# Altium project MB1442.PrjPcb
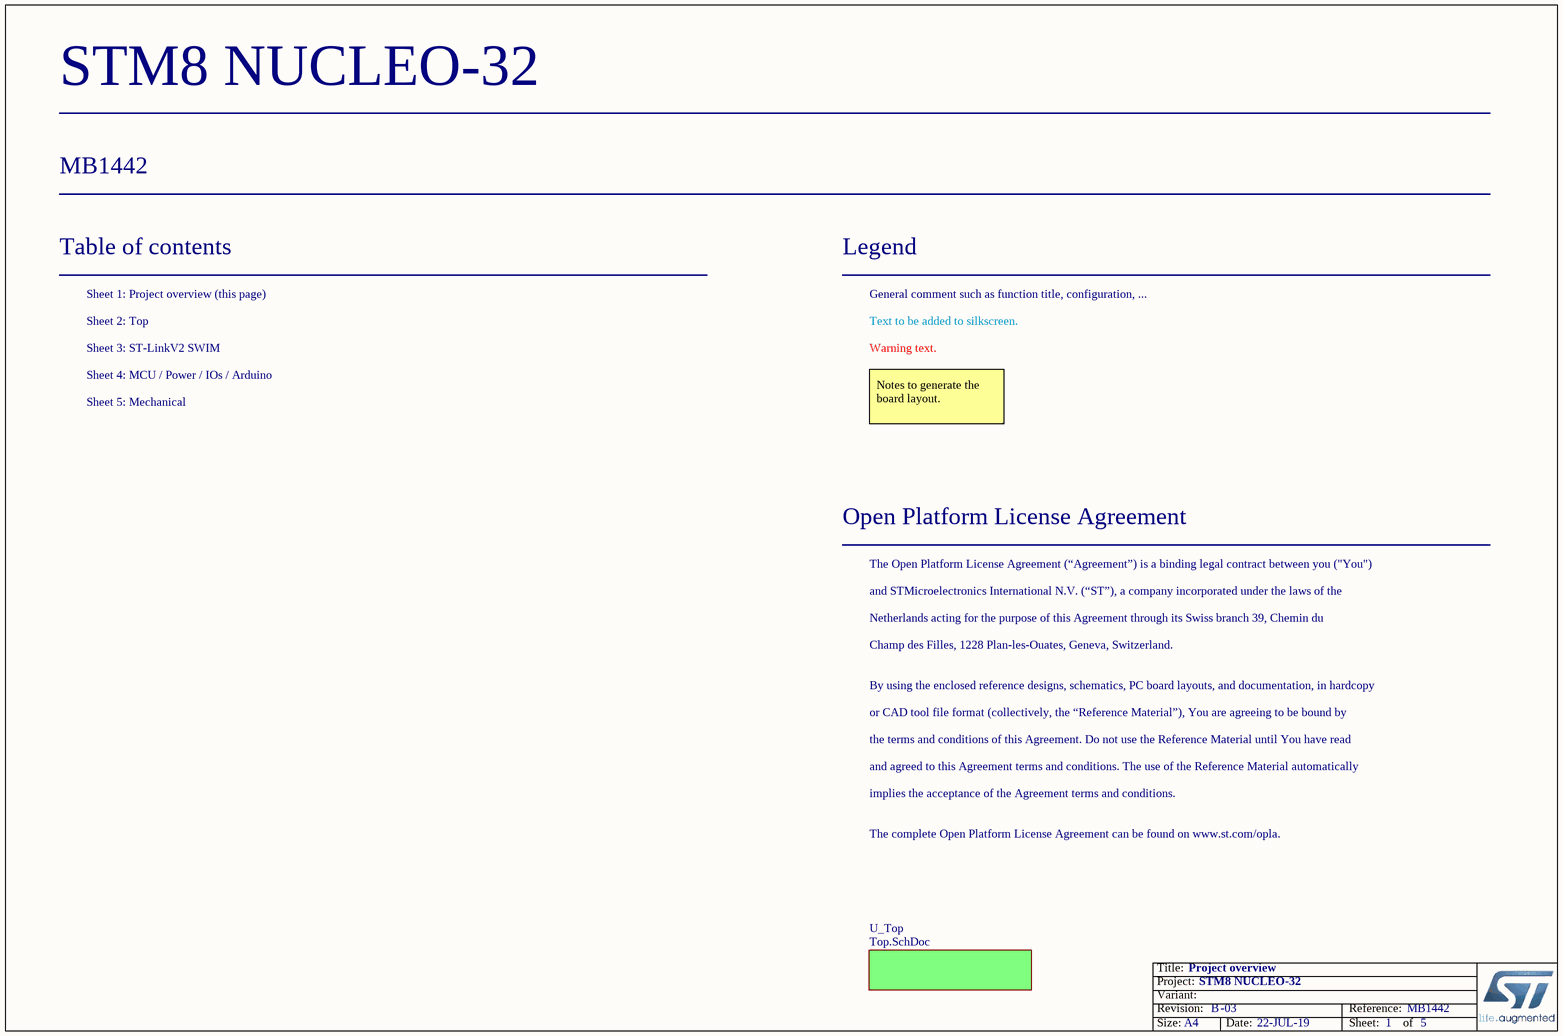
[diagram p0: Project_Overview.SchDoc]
Board_Assembly_Revision: 03; Board_Document_Date: 22-JUL-19; Board_Name: STM8 NUCLEO-32; Board_PCB_Revision: B; Board_Reference: MB1442
5 sheets, 96 parts. Net scope: flat (ports and power ports of the same name join across sheets).
Board file: MB1442.PcbDoc
Sheets:
  Project_Overview.SchDoc
    U_Top = Top.SchDoc
      U_ST-LinkV2-1_SWIM = ST-LinkV2-1_SWIM.SchDoc
      U_MCU_Power_IOs_Arduino = MCU_Power_IOs_Arduino.SchDoc
      U_Mechanical = Mechanical.SchDoc

## Sheet Project_Overview.SchDoc: Project overview
size A4; Date: Not used; ApprovedBy: Not used; CheckedBy: Not used; Author: Not used; CompanyName: STMicroelectronics; DrawnBy: Not used; Engineer: Not used; Organization: Not used; Address1: Not used; Address2: Not used; Address3: Not used; Address4: Not used; DocumentNumber: Not used; Revision: Not used; SheetNumber: 1; SheetTotal: 5

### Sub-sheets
U_Top = Top.SchDoc: no entries

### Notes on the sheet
- Table of contents
- Sheet 1: Project overview (this page)
- Legend
- General comment such as function title, configuration, ...
- Sheet 2: Top
- Sheet 3: ST-LinkV2 SWIM
- Sheet 4: MCU / Power / IOs / Arduino
- Text to be added to silkscreen.
- Warning text.
- Sheet 5: Mechanical
- Notes to generate the board layout.
- Open Platform License Agreement
- The Open Platform License Agreement (“Agreement”) is a binding legal contract between you ("You")
- and STMicroelectronics International N.V. (“ST”), a company incorporated under the laws of the
- Netherlands acting for the purpose of this Agreement through its Swiss branch 39, Chemin du
- Champ des Filles, 1228 Plan-les-Ouates, Geneva, Switzerland.
- By using the enclosed reference designs, schematics, PC board layouts, and documentation, in hardcopy
- or CAD tool file format (collectively, the “Reference Material”), You are agreeing to be bound by
- the terms and conditions of this Agreement. Do not use the Reference Material until You have read
- and agreed to this Agreement terms and conditions. The use of the Reference Material automatically
- implies the acceptance of the Agreement terms and conditions.
- The complete Open Platform License Agreement can be found on www.st.com/opla.

## Sheet Top.SchDoc: Top
size A4; Date: Not used; ApprovedBy: Not used; CheckedBy: Not used; Author: Not used; CompanyName: STMicroelectronics; DrawnBy: Not used; Engineer: Not used; Organization: Not used; Address1: Not used; Address2: Not used; Address3: Not used; Address4: Not used; DocumentNumber: Not used; Revision: Not used; SheetNumber: 2; SheetTotal: 5
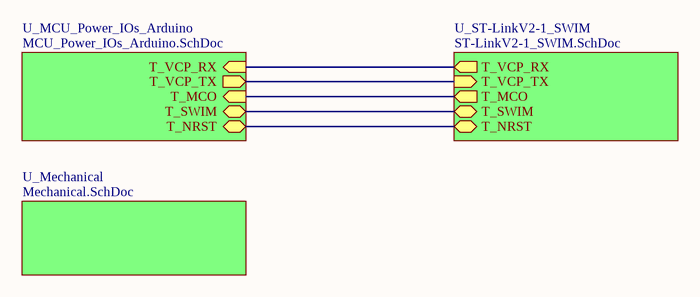
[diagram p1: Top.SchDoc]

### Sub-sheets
U_MCU_Power_IOs_Arduino = MCU_Power_IOs_Arduino.SchDoc: T_SWIM (bidir), T_NRST (bidir), T_MCO (in), T_VCP_RX (in), T_VCP_TX (out)
U_Mechanical = Mechanical.SchDoc: no entries
U_ST-LinkV2-1_SWIM = ST-LinkV2-1_SWIM.SchDoc: T_VCP_RX (out), T_VCP_TX (in), T_MCO (out), T_SWIM (bidir), T_NRST (bidir)

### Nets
(unnamed): sheet U_ST-LinkV2-1_SWIM/T_VCP_RX, sheet U_MCU_Power_IOs_Arduino/T_VCP_RX
(unnamed): sheet U_ST-LinkV2-1_SWIM/T_VCP_TX, sheet U_MCU_Power_IOs_Arduino/T_VCP_TX  [a separate net that carries the same name]
(unnamed): sheet U_ST-LinkV2-1_SWIM/T_MCO, sheet U_MCU_Power_IOs_Arduino/T_MCO  [a separate net that carries the same name]
(unnamed): sheet U_ST-LinkV2-1_SWIM/T_SWIM, sheet U_MCU_Power_IOs_Arduino/T_SWIM  [a separate net that carries the same name]
(unnamed): sheet U_ST-LinkV2-1_SWIM/T_NRST, sheet U_MCU_Power_IOs_Arduino/T_NRST  [a separate net that carries the same name]

## Sheet ST-LinkV2-1_SWIM.SchDoc: ST-Link/V2-1 SWIM
size A4; Date: Not used; ApprovedBy: Not used; CheckedBy: Not used; Author: Not used; CompanyName: STMicroelectronics; DrawnBy: Not used; Engineer: Not used; Organization: Not used; Address1: Not used; Address2: Not used; Address3: Not used; Address4: Not used; DocumentNumber: Not used; Revision: Not used; SheetNumber: 4; SheetTotal: 5
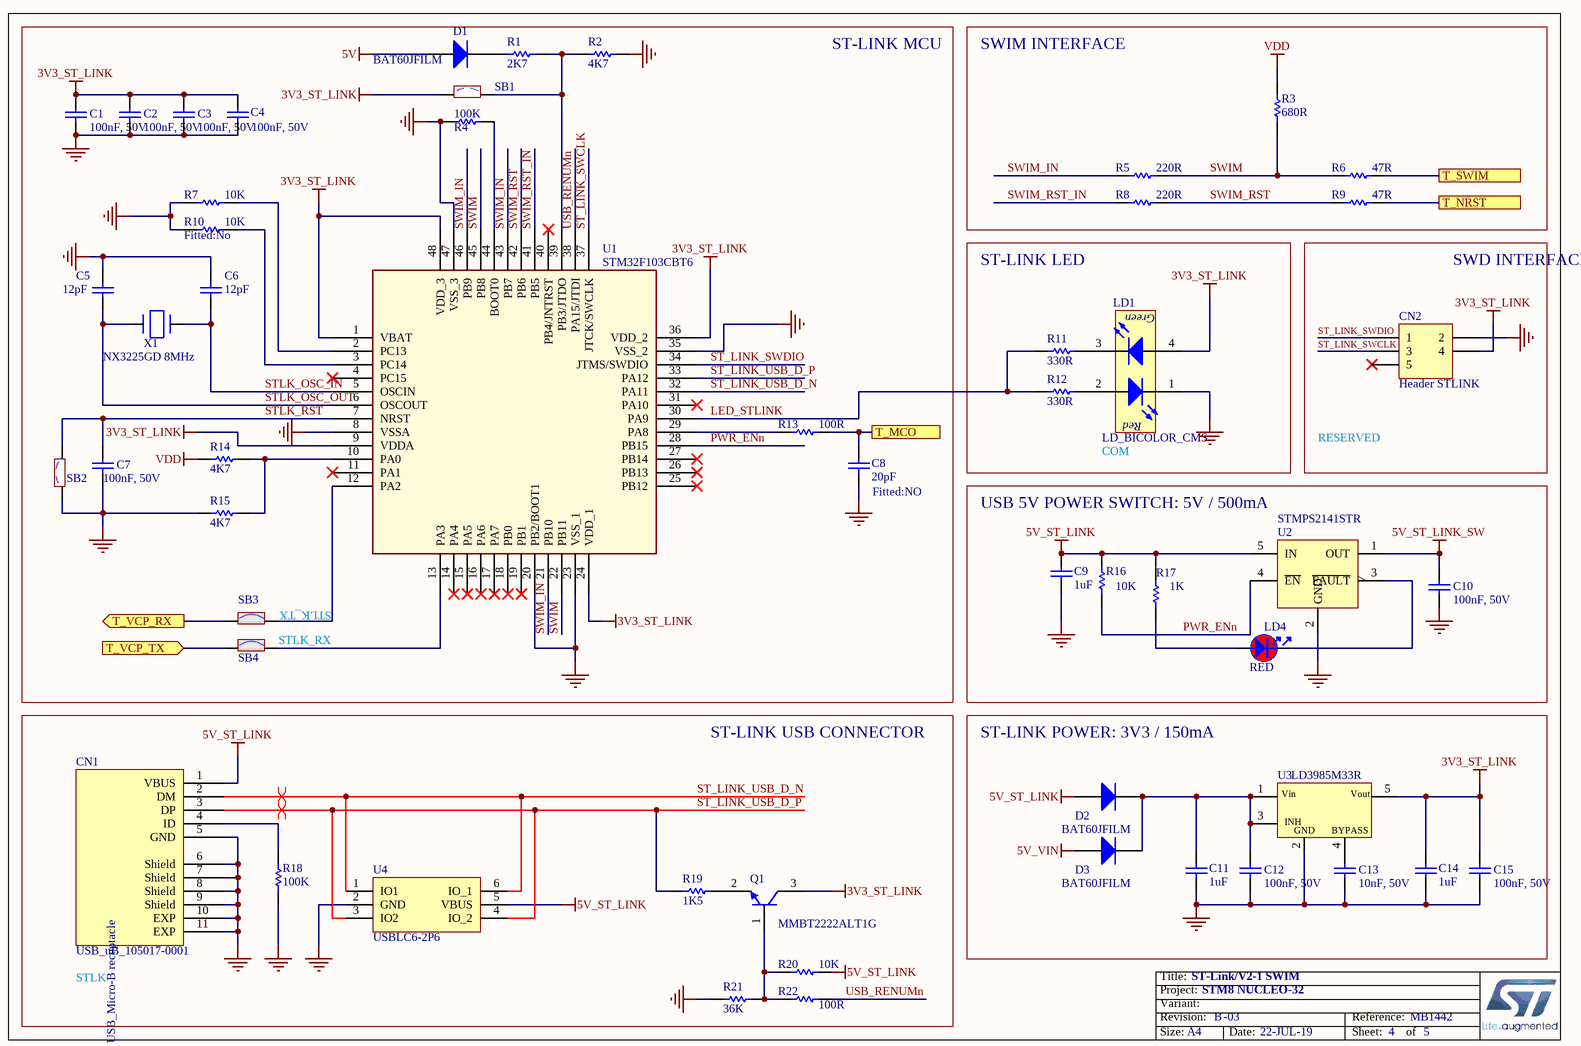
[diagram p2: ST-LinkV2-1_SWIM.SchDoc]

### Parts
C1  value 100nF, 50V  [C0603]  (hidden comment: Capacitor)
C2  value 100nF, 50V  [C0603]  (hidden comment: Capacitor)
C3  value 100nF, 50V  [C0603]  (hidden comment: Capacitor)
C4  value 100nF, 50V  [C0603]  (hidden comment: Capacitor)
C5  value 12pF  [C0402]  (hidden comment: Capacitor)
C6  value 12pF  [C0402]  (hidden comment: Capacitor)
C7  value 100nF, 50V  [C0603]  (hidden comment: Capacitor)
C8  value 20pF  [C0603]  (hidden comment: Capacitor)
C9  value 1uF  [C0603]  (hidden comment: Capacitor)
C10  value 100nF, 50V  [C0603]  (hidden comment: Capacitor)
C11  value 1uF  [C0603]  (hidden comment: Capacitor)
C12  value 100nF, 50V  [C0603]  (hidden comment: Capacitor)
C13  value 10nF, 50V  [C0603]  (hidden comment: Capacitor)
C14  value 1uF  [C0603]  (hidden comment: Capacitor)
C15  value 100nF, 50V  [C0603]  (hidden comment: Capacitor)
CN1  value USB_uB_105017-0001  [CON_USBMICROB_MOLEX_105017-0001_H2P90]  (hidden comment: USB_uB_105017.0001)
CN2  Header STLINK  [HDR_1x5_2R54_V_M]
D1  BAT60JFILM  [DIO_SOD323]
D2  BAT60JFILM  [DIO_SOD323]
D3  BAT60JFILM  [DIO_SOD323]
LD1  LD_BICOLOR_CMS  [LED_BI-GR_HSMF-A201-A00J1]
LD4  value RED  [LED_0603_RED_H0P4]  (hidden comment: LED_red)
Q1  value MMBT2222ALT1G  [NPN_SOT23]  (hidden comment: 9013-SOT23)
R1  value 2K7  [R0603]  (hidden comment: Resistor)
R2  value 4K7  [R0603]  (hidden comment: Resistor)
R3  value 680R  [R0603]  (hidden comment: Resistor)
R4  value 100K  [R0603]  (hidden comment: Resistor)
R5  value 220R  [R0603]  (hidden comment: Resistor)
R6  value 47R  [R0603]  (hidden comment: Resistor)
R7  value 10K  [R0603]  (hidden comment: Resistor)
R8  value 220R  [R0603]  (hidden comment: Resistor)
R9  value 47R  [R0603]  (hidden comment: Resistor)
R10  value 10K  [R0603]  (hidden comment: Resistor)
R11  value 330R  [R0603]  (hidden comment: Resistor)
R12  value 330R  [R0603]  (hidden comment: Resistor)
R13  value 100R  [R0603]  (hidden comment: Resistor)
R14  value 4K7  [R0603]  (hidden comment: Resistor)
R15  value 4K7  [R0603]  (hidden comment: Resistor)
R16  value 10K  [R0603]  (hidden comment: Resistor)
R17  value 1K  [R0603]  (hidden comment: Resistor)
R18  value 100K  [R0603]  (hidden comment: Resistor)
R19  value 1K5  [R0603]  (hidden comment: Resistor)
R20  value 10K  [R0603]  (hidden comment: Resistor)
R21  value 36K  [R0603]  (hidden comment: Resistor)
R22  value 100R  [R0603]  (hidden comment: Resistor)
SB1  SB_OFF  [SOLDER-BRIDGE_R0603-0R]  (value not drawn)
SB2  SB_OFF  [SOLDER-BRIDGE_R0603-0R]  (value not drawn)
SB3  SB_ON  [SOLDER-BRIDGE_R0603-0R]  (value not drawn)
SB4  SB_ON  [SOLDER-BRIDGE_R0603-0R]  (value not drawn)
U1  STM32F103CBT6  [ICC_LQFP48_7X7_P050]
U2  STMPS2141STR  [MOS_SOT23-5L]
U3  LD3985M33R  [REG_SOT23-5L]
U4  USBLC6-2P6  [ESD_SOT666]
X1  value NX3225GD 8MHz  [CRY_NX3225GD_2P]  (hidden comment: XTAL_2_PINS)

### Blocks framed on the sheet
ST-LINK MCU: C1-C8 D1 R1 R2 R4 R7 R10 R13-R15 SB1-SB4 U1 X1
SWIM INTERFACE: R3 R5 R6 R8 R9
ST-LINK LED: LD1 R11 R12
SWD INTERFACE: CN2
USB 5V POWER SWITCH: 5V / 500mA: C9 C10 LD4 R16 R17 U2
ST-LINK USB CONNECTOR: CN1 Q1 R18-R22 U4
ST-LINK POWER: 3V3 / 150mA: C11-C15 D2 D3 U3

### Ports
T_MCO, T_NRST, T_SWIM, T_VCP_RX (out), T_VCP_TX (in)

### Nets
3V3_ST_LINK: C1.2 C2.2 C3.2 C4.2 C14.2 C15.2 CN2.4 LD1.4(YellowGreen_anode) Q1.3(C) SB1.1 U1.1(VBAT) U1.9(VDDA) U1.24(VDD_1) U1.36(VDD_2) U1.48(VDD_3) U3.5(Vout)
5V: D1.1(A)
5V_ST_LINK: C9.2 CN1.1(VBUS) D2.1(A) R16.2 R17.2 R20.2 U2.5(IN) U4.5(VBUS)
5V_ST_LINK_SW: C10.2 U2.1(OUT)
5V_VIN: D3.1(A)
GND: C1.1 C2.1 C3.1 C4.1 C5.2 C6.2 C7.1 C8.1 C9.1 C10.1 C11.1 C12.1 C13.1 C14.1 C15.1 CN1.5(GND) CN1.6(Shield) CN1.7(Shield) CN1.8(Shield) CN1.9(Shield) CN1.10(EXP) CN1.11(EXP) CN2.2 LD1.1(RED_cathode) R2.2 R4.1 R7.1 R10.1 R15.1 R18.1 R21.1 SB2.1 U1.8(VSSA) U1.20(PB2/BOOT1) U1.23(VSS_1) U1.35(VSS_2) U1.47(VSS_3) U2.2(GND) U3.2(GND) U4.2(GND)
VDD: R3.2 R14.1
LED_STLINK: R11.1 R12.1 U1.30(PA9)
PWR_ENn: R16.1 U1.28(PB15) U2.4(~{EN})
ST_LINK_SWCLK: CN2.3 U1.37(JTCK/SWCLK)
ST_LINK_SWDIO: CN2.1 U1.34(JTMS/SWDIO)
ST_LINK_USB_D_N: CN1.2(DM) U1.32(PA11) U4.1(IO1) U4.6(IO_1)
ST_LINK_USB_D_P: CN1.3(DP) R19.1 U1.33(PA12) U4.3(IO2) U4.4(IO_2)
STLK_OSC_IN: C6.1 U1.5(OSCIN) X1.1(X1)
STLK_OSC_OUT: C5.1 U1.6(OSCOUT) X1.2(X2)
STLK_RST: C7.2 SB2.2 U1.7(NRST)
SWIM: R3.1 R5.2 R6.1 U1.22(PB11) U1.45(PB8)
SWIM_IN: R5.1 U1.21(PB10) U1.43(PB7) U1.46(PB9)
SWIM_RST: R8.2 R9.1 U1.42(PB6)
SWIM_RST_IN: R8.1 U1.41(PB5)
T_MCO: C8.2 R13.2 ; port T_MCO
T_NRST: R9.2 ; port T_NRST
T_SWIM: R6.2 ; port T_SWIM
T_VCP_RX: SB3.1 ; port T_VCP_RX
T_VCP_TX: SB4.1 ; port T_VCP_TX
USB_RENUMn: R22.2 U1.38(PA15/JTDI)
NetC11_2: C11.2 C12.2 D2.2(K) D3.2(K) U3.1(Vin) U3.3(CE)
NetC13_2: C13.2 U3.4(BYPASS)
NetCN1_4: CN1.4(ID) R18.2
NetD1_2: D1.2(K) R1.1
NetLD1_2: LD1.2(Red_anode) R12.2
NetLD1_3: LD1.3(YellowGreen_cathode) R11.2
NetLD4_1: LD4.1 R17.1
NetLD4_2: LD4.2 U2.3(~{FAULT})
NetQ1_1: Q1.1(B) R20.1 R21.2 R22.1
NetQ1_2: Q1.2(E) R19.2
NetR1_2: R1.2 R2.1 SB1.2 U1.39(PB3/JTDO)
NetR4_2: R4.2 U1.44(BOOT0)
NetR7_2: R7.2 U1.2(PC13)
NetR10_2: R10.2 U1.3(PC14)
NetR13_1: R13.1 U1.29(PA8)
NetR14_2: R14.2 R15.2 U1.10(PA0)
NetSB3_2: SB3.2 U1.12(PA2)
NetSB4_2: SB4.2 U1.13(PA3)

Not connected (* = marked no-connect by the designer): CN2 5*; U1 4(PC15)* 11(PA1)* 14(PA4)* 15(PA5)* 16(PA6)* 17(PA7)* 18(PB0)* 19(PB1)* 25(PB12)* 26(PB13)* 27(PB14)* 31(PA10)* 40(PB4/JNTRST)*

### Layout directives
differential pair: ST_LINK_USB_D_N, ST_LINK_USB_D_P

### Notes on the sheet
- (near R10) Fitted:No
- COM
- RESERVED
- (near C8) Fitted:NO
- STLK_RX
- STLK_TX
- STLK

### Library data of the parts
C1-C4 C7 C10 C12 C15 = MCD-01099: Capacitor,100nF,50V,X7R,10%,0603; Manufacturer_Part_Number: CC0603KRX7R9BB104; Manufacturer: YAGEO; Provided_By: SUBCO
C5 C6 = MCD-00200: Capacitor, MLCC, 12pF, 50V, NPO, 5%, 0402, T=0,5mm; Manufacturer_Part_Number: CC0402JRNPO9BN120; Manufacturer: YAGEO; Provided_By: SUBCO; ECCN_US: EAR99; ECCN_EU: NEC
C8 = MCD-00638: Capacitor, MLCC, 20pF, 50V, NPO, 5%, 0603, T=0,8mm; Manufacturer_Part_Number: CC0603JRNPO9BN200; Manufacturer: YAGEO; ECCN_US: EAR99; ECCN_EU: NEC; Provided_By: SUBCO
C9 C11 C14 = MCD-01053: Capacitor, C-series, X5R, 1µF, 50V, 10%, 0603, T=0.8mm; Manufacturer_Part_Number: C1608X5R1H105K080AB; Manufacturer: TDK; ECCN_US: EAR99; ECCN_EU: NEC; Provided_By: SUBCO
C13 = MCD-01102: Capacitor,10nF,50V,X7R,10%,0603; Manufacturer_Part_Number: CC0603KRX7R9BB103; Manufacturer: YAGEO; Provided_By: SUBCO
CN1 = MCD-00028: USB-MICRO-B, 0.65mm, RA, SMT, Bottom Mount,; Part_Type: Connector; Manufacturer_Part_Number: 1050170001; Manufacturer: MOLEX; Provided_By: SUBCO
CN2 = MCD-01399: Header 5 pads for ST-LINK prog. Not fitted; Part_Type: Mechanical; Provided_By: SUBCO
D1-D3 = MCD-00034: Part_Type: Diode; Manufacturer: STMICROELECTRONICS; BMS_Part_Number: 9151097; ECCN_US: EAR99; ECCN_EU: NEC; Provided_By: SUBCO with ST control
LD1 = MCD-00051: LED Bicolor; Part_Type: Display; Manufacturer_Part_Number: HSMF-A201-A00J1; Manufacturer: AVAGO TECHNOLOGIES; Alternate_Manufacturer_Part_Number: LE-RGW35280; Alternate_Manufacturer: EVERLUCK; ECCN_US: EAR99; ECCN_EU: NEC; Provided_By: SUBCO
LD4 = MCD-00322: LED, Red, 0603; Part_Type: Display; Manufacturer_Part_Number: 19-217/R6C-AL1M2VY/3T; Manufacturer: EVERLIGHT; ECCN_US: EAR99; ECCN_EU: NEC; Provided_By: SUBCO
Q1 = MCD-01737: NPN Bipolar Transistor; Part_Type: IC; Manufacturer: ON SEMICONDUCTOR; ECCN_US: EAR99; ECCN_EU: NEC; Provided_By: SUBCO
R1 = MCD-00218: Resistor,2K7,0603,1%,1/10W; Manufacturer_Part_Number: RC0603FR-072K7L; Manufacturer: YAGEO; BMS_Part_Number: 9129767; ECCN_US: EAR99; ECCN_EU: NEC; Provided_By: SUBCO
R2 R14 R15 = MCD-00219: Resistor,4K7,0603,1%,1/10W; Manufacturer_Part_Number: RC0603FR-074K7L; Manufacturer: YAGEO; ECCN_US: EAR99; ECCN_EU: NEC; Provided_By: SUBCO
R3 = MCD-00508: Resistor,680R,0603,1%,1/10W; Manufacturer_Part_Number: RC0603FR-07680RL; Manufacturer: YAGEO; ECCN_US: EAR99; ECCN_EU: NEC; Provided_By: SUBCO
R4 R18 = MCD-00223: Resistor,100K,0603,1%,1/10W; Manufacturer_Part_Number: RC0603FR-07100KL; Manufacturer: YAGEO; ECCN_US: EAR99; ECCN_EU: NEC; Provided_By: SUBCO
R5 R8 = MCD-00428: Resistor,220R,0603,1%,1/10W; Manufacturer_Part_Number: RC0603FR-07220RL; Manufacturer: YAGEO; BMS_Part_Number: 9129728; ECCN_US: EAR99; ECCN_EU: NEC; Provided_By: SUBCO
R6 R9 = MCD-00482: Resistor,47R,0603,1%,1/10W; Manufacturer_Part_Number: RC0603FR-0747RL; Manufacturer: YAGEO; ECCN_US: EAR99; ECCN_EU: NEC; Provided_By: SUBCO
R7 R10 R16 R20 = MCD-00220: Resistor,10K,0603,1%,1/10W; Manufacturer_Part_Number: RC0603FR-0710KL; Manufacturer: YAGEO; ECCN_US: EAR99; ECCN_EU: NEC; Provided_By: SUBCO
R11 R12 = MCD-00197: Resistor,330R,0603,1%,1/10W; Manufacturer_Part_Number: RC0603FR-07330RL; Manufacturer: YAGEO; BMS_Part_Number: 9129729; ECCN_US: EAR99; ECCN_EU: NEC; Provided_By: SUBCO
R13 R22 = MCD-00224: Resistor,100R,0603,1%,1/10W; Manufacturer_Part_Number: RC0603FR-07100RL; Manufacturer: YAGEO; ECCN_US: EAR99; ECCN_EU: NEC; Provided_By: SUBCO
R17 = MCD-00070: Resistor,1K,0603,1%,1/10W; Manufacturer_Part_Number: RC0603FR-071KL; Manufacturer: YAGEO; ECCN_US: EAR99; ECCN_EU: NEC; Provided_By: SUBCO
R19 = MCD-00217: Resistor,1K5,0603,1%,1/10W; Manufacturer_Part_Number: RC0603FR-071K5L; Manufacturer: YAGEO; BMS_Part_Number: 9129766; ECCN_US: EAR99; ECCN_EU: NEC; Provided_By: SUBCO
R21 = MCD-00221: Resistor,36K,0603,1%,1/10W; Manufacturer_Part_Number: RC0603FR-0736KL; Manufacturer: YAGEO; ECCN_US: EAR99; ECCN_EU: NEC; Provided_By: SUBCO
SB1 SB2 = MCD-00072: Solder Bridge OFF; Part_Type: Mechanical; Manufacturer_Part_Number: RC0603JR-070RL; Manufacturer: YAGEO; Provided_By: SUBCO
SB3 SB4 = MCD-00071: Solder Bridge ON; Part_Type: Mechanical; Manufacturer_Part_Number: RC0603JR-070RL; Manufacturer: YAGEO; Provided_By: SUBCO
U1 = MCD-00085: Medium-density performance line ARM-based 32-bit MCU with 128KB Flash; Part_Type: IC; Manufacturer: STMICROELECTRONICS; BMS_Part_Number: 9175111; ECCN_US: 3A991A2; ECCN_EU: NEC; Provided_By: SUBCO with ST control
U2 = MCD-00083: Enhanced single channel power switches with active low enable pin; Part_Type: IC; Manufacturer: STMICROELECTRONICS; Alternate_Manufacturer_Part_Number: TPS2041C; Alternate_Manufacturer: TEXAS INSTRUMENTS; BMS_Part_Number: 9159003; ECCN_US: EAR99; ECCN_EU: NEC; Provided_By: SUBCO with ST control
U3 = MCD-00086: Ultra low drop-low noise BiCMOS voltage, regulators low ESR capacitors compatible; Part_Type: IC; Manufacturer: STMICROELECTRONICS; BMS_Part_Number: 9176161; ECCN_US: EAR99; ECCN_EU: NEC; Provided_By: SUBCO with ST control
U4 = MCD-00169: USB OTG FS ESD protection; Part_Type: IC; Manufacturer: STMICROELECTRONICS; BMS_Part_Number: 9151057; ECCN_US: EAR99; ECCN_EU: NEC; Provided_By: SUBCO with ST control
X1 = MCD-00092: Crystal 8MHz, 8pF, +-20ppm, 500ohms max,  SMD; Part_Type: Crystal_Osc; Manufacturer_Part_Number: NX3225GD 8MHz EXS00A-CG04874; Manufacturer: NDK; BMS_Part_Number: 9157029; ECCN_US: EAR99; ECCN_EU: NEC; Provided_By: SUBCO

## Sheet MCU_Power_IOs_Arduino.SchDoc: MCU/Power/IOs/Arduino
size A4; Date: Not used; ApprovedBy: Not used; CheckedBy: Not used; Author: Not used; CompanyName: STMicroelectronics; DrawnBy: Not used; Engineer: Not used; Organization: Not used; Address1: Not used; Address2: Not used; Address3: Not used; Address4: Not used; DocumentNumber: Not used; Revision: Not used; SheetNumber: 3; SheetTotal: 5
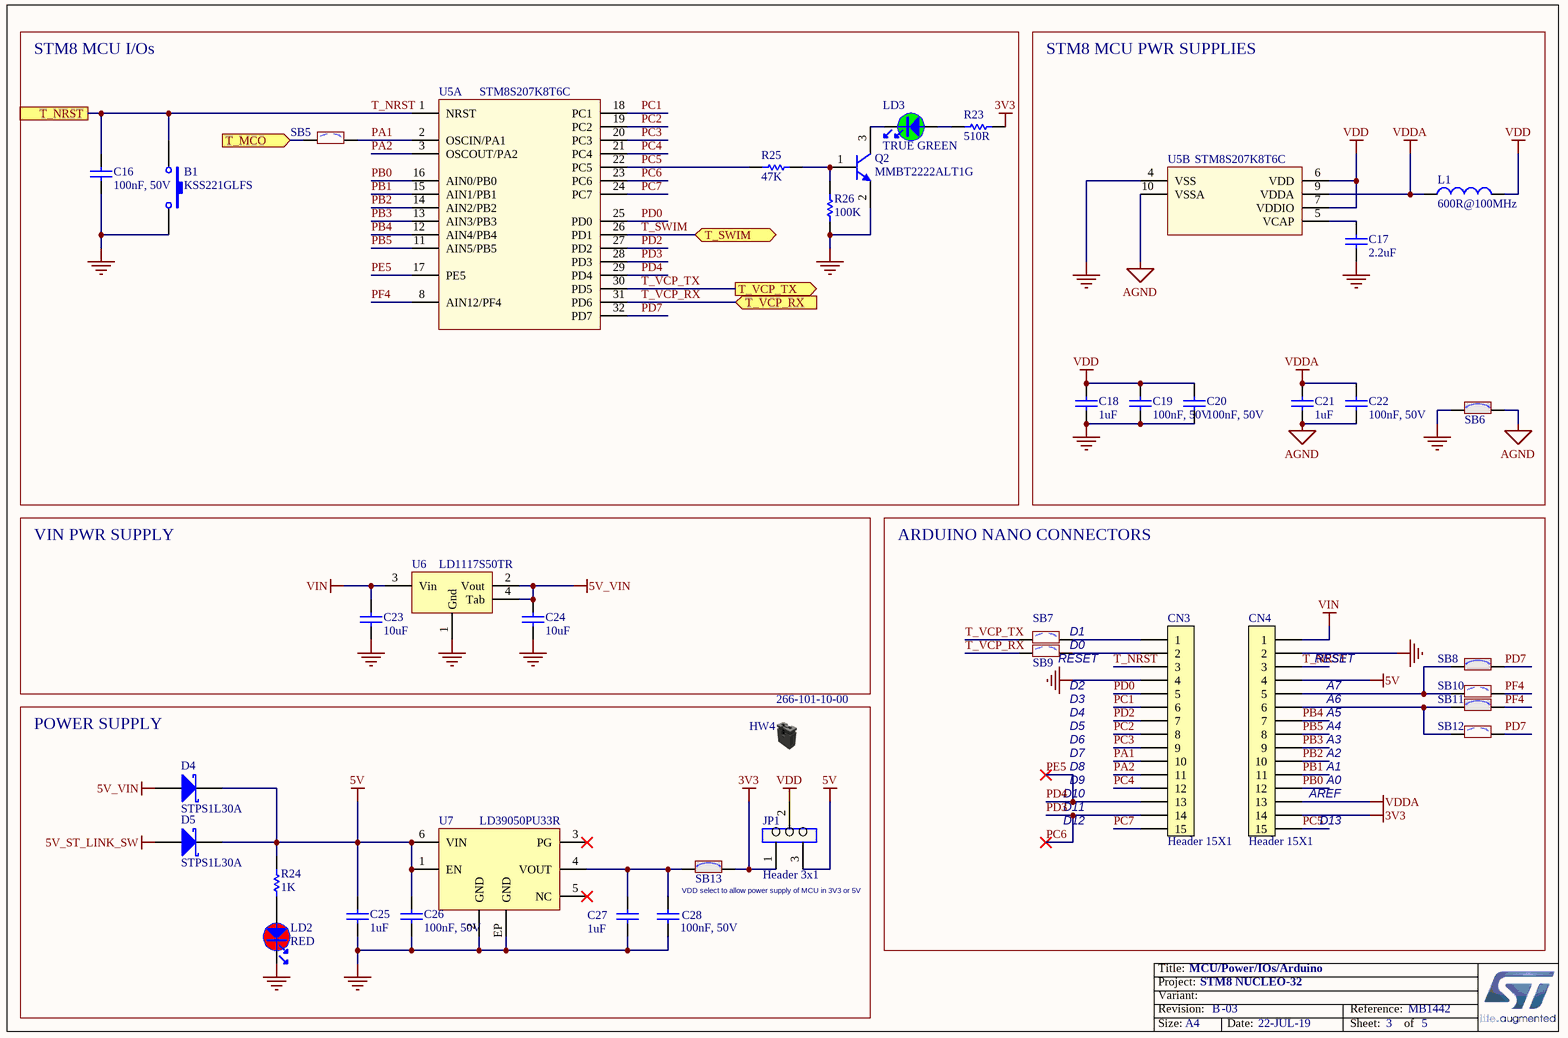
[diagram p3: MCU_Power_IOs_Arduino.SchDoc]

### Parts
B1  value KSS221GLFS  [SWI_C&K_ITT_KSS221G]  (hidden comment: SW-PB)
C16  value 100nF, 50V  [C0603]  (hidden comment: Capacitor)
C17  value 2.2uF  [C0603]  (hidden comment: Capacitor)
C18  value 1uF  [C0603]  (hidden comment: Capacitor)
C19  value 100nF, 50V  [C0603]  (hidden comment: Capacitor)
C20  value 100nF, 50V  [C0603]  (hidden comment: Capacitor)
C21  value 1uF  [C0603]  (hidden comment: Capacitor)
C22  value 100nF, 50V  [C0603]  (hidden comment: Capacitor)
C23  value 10uF  [C0603]  (hidden comment: Capacitor)
C24  value 10uF  [C0603]  (hidden comment: Capacitor)
C25  value 1uF  [C0603]  (hidden comment: Capacitor)
C26  value 100nF, 50V  [C0603]  (hidden comment: Capacitor)
C27  value 1uF  [C0603]  (hidden comment: Capacitor)
C28  value 100nF, 50V  [C0603]  (hidden comment: Capacitor)
CN3  Header 15x1  [CON_LYCN_313115S161145]
CN4  Header 15x1  [CON_LYCN_313115S161145]
D4  value STPS1L30A  [DIO_SMA_1A_2K]  (hidden comment: STPS1L40M)
D5  value STPS1L30A  [DIO_SMA_1A_2K]  (hidden comment: STPS1L40M)
HW4  value 266-101-10-00  (hidden comment: Shunt Black 1.27mm 266-101-10-00)  (mechanical)
JP1  value Header 3x1  [CON_SAMTEC_TMS-103-03-L-S-RA]  (hidden comment: Jumper_Header 3x1)
L1  value 600R@100MHz  [L0603]  (hidden comment: BEAD)
LD2  value RED  [LED_0603_RED_H0P4]  (hidden comment: LED_red)
LD3  value TRUE GREEN  [LED_0603_VISHAY_VLMTG1300-GS08_GREEN_1A2K_H0P8]  (hidden comment: LED_green)
Q2  value MMBT2222ALT1G  [NPN_SOT23]  (hidden comment: 9013-SOT23)
R23  value 510R  [R0603]  (hidden comment: Resistor)
R24  value 1K  [R0603]  (hidden comment: Resistor)
R25  value 47K  [R0603]  (hidden comment: Resistor)
R26  value 100K  [R0603]  (hidden comment: Resistor)
SB5  SB_OFF  [SOLDER-BRIDGE_R0603-0R]  (value not drawn)
SB6  SB_ON  [SOLDER-BRIDGE_R0603-0R]  (value not drawn)
SB7  SB_OFF  [SOLDER-BRIDGE_R0603-0R]  (value not drawn)
SB8  SB_ON  [SOLDER-BRIDGE_R0603-0R]  (value not drawn)
SB9  SB_OFF  [SOLDER-BRIDGE_R0603-0R]  (value not drawn)
SB10  SB_OFF  [SOLDER-BRIDGE_R0603-0R]  (value not drawn)
SB11  SB_ON  [SOLDER-BRIDGE_R0603-0R]  (value not drawn)
SB12  SB_OFF  [SOLDER-BRIDGE_R0603-0R]  (value not drawn)
SB13  SB_ON  [SOLDER-BRIDGE_R0603-0R]  (value not drawn)
U5  value STM8S207K8T6C  [TQFP80P900X900X160-32N]  (hidden comment: STM8S207K8T6)  (parts A,B of 2)
U6  LD1117S50TR  [REG_SOT223-TAB]
U7  LD39050PU33R  [ICC_DFN6-EPAD_3X3_P095]

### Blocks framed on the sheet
STM8 MCU I/Os: B1 C16 LD3 Q2 R23 R25 R26 SB5 U5
STM8 MCU PWR SUPPLIES: C17-C22 L1 SB6 U5
VIN PWR SUPPLY: C23 C24 U6
ARDUINO NANO CONNECTORS: CN3 CN4 SB7-SB12
POWER SUPPLY: C25-C28 D4 D5 HW4 JP1 LD2 R24 SB13 U7

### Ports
T_MCO (in), T_NRST, T_SWIM (bidir), T_VCP_RX (in), T_VCP_TX (out)

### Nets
3V3: CN4.14 JP1.1 R23.2 SB13.2
5V: C25.2 C26.1 CN4.4 D4.2(K) D5.2(K) JP1.3 R24.2 U7.1(EN) U7.6(VIN)
5V_ST_LINK_SW: D5.1(A)
5V_VIN: C24.2 D4.1(A) U6.2(Vout) U6.4(Tab)
AGND: C21.1 C22.2 SB6.2 U5.10(VSSA)
GND: B1.2 C16.1 C17.1 C18.1 C19.2 C20.2 C23.1 C24.1 C25.1 C26.2 C27.1 C28.2 CN3.4 CN4.2 LD2.2 Q2.2(E) R26.2 SB6.1 U5.4(VSS) U6.1(Gnd) U7.2(GND) U7.EP(GND)
VDD: C18.2 C19.1 C20.1 JP1.2 L1.2 U5.6(VDD) U5.7(VDDIO)
VDDA: C21.2 C22.1 CN4.13 L1.1 U5.9(VDDA)
VIN: C23.2 CN4.1 U6.3(Vin)
PA1: CN3.10 SB5.2 U5.2(OSCIN/PA1)
PA2: CN3.11 U5.3(OSCOUT/PA2)
PB0: CN4.12 U5.16(AIN0/PB0)
PB1: CN4.11 U5.15(AIN1/PB1)
PB2: CN4.10 U5.14(AIN2/PB2)
PB3: CN4.9 U5.13(AIN3/PB3)
PB4: CN4.7 U5.12(AIN4/PB4)
PB5: CN4.8 U5.11(AIN5/PB5)
PC1: CN3.6 U5.18(PC1)
PC2: CN3.8 U5.19(PC2)
PC3: CN3.9 U5.20(PC3)
PC4: CN3.12 U5.21(PC4)
PC5: CN4.15 R25.1 U5.22(PC5)
PC6: CN3.14 U5.23(PC6) U5.28(PD3)  [also labelled PD3]
PC7: CN3.15 U5.24(PC7)
PD0: CN3.5 U5.25(PD0)
PD2: CN3.7 U5.27(PD2)
PD4: CN3.13 U5.17(PE5) U5.29(PD4)  [also labelled PE5]
PD7: SB8.2 SB12.2 U5.32(PD7)
PF4: SB10.2 SB11.2 U5.8(AIN12/PF4)
T_MCO: SB5.1 ; port T_MCO
T_NRST: B1.1 C16.2 CN3.3 CN4.3 U5.1(NRST) ; port T_NRST
T_SWIM: U5.26(PD1) ; port T_SWIM
T_VCP_RX: SB9.1 U5.31(PD6) ; port T_VCP_RX
T_VCP_TX: SB7.1 U5.30(PD5) ; port T_VCP_TX
NetC17_2: C17.2 U5.5(VCAP)
NetC27_2: C27.2 C28.1 SB13.1 U7.4(VOUT)
NetCN3_1: CN3.1 SB7.2
NetCN3_2: CN3.2 SB9.2
NetCN4_5: CN4.5 SB8.1 SB10.1
NetCN4_6: CN4.6 SB11.1 SB12.1
NetLD2_1: LD2.1 R24.1
NetLD3_1: LD3.1 R23.1
NetLD3_2: LD3.2 Q2.3(C)
NetQ2_1: Q2.1(B) R25.2 R26.1

Not connected (* = marked no-connect by the designer): U7 3(PG)* 5(NC)*

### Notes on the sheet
- D1
- D0
- D2
- D3
- D4
- RESET
- A6
- A5
- A7
- D6
- D5
- D7
- D8
- D9
- A4
- A3
- A2
- A1
- A0
- D10
- D11
- D12
- D13
- AREF
- VDD select to allow power supply of MCU in 3V3 or 5V

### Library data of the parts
B1 = MCD-01335: Subminiature Side Actuated Tact Switch for SMT - KSS series - 2.0 Newtons - Gull wing, SPST; Part_Type: Misc; Manufacturer: C&K; Provided_By: SUBCO; ECCN_US: EAR99; ECCN_EU: NEC
C16 C19 C20 C22 C26 C28 = MCD-01099: as C1 on sheet ST-LinkV2-1_SWIM
C17 = MCD-00654: Capacitor,2.2uF,16V, X5R,10%,0603,YAGEO; Manufacturer_Part_Number: CC0603KRX5R7BB225; ECCN_US: EAR99; ECCN_EU: NEC; Provided_By: SUBCO
C18 C21 C25 C27 = MCD-01053: as C9 on sheet ST-LinkV2-1_SWIM
C23 C24 = MCD-01124: Capacitor, MLCC, 10µF, 10V, X5R, 10%, 0603, T=0.8mm; Manufacturer_Part_Number: GRM188R61A106KAAL; Manufacturer: MURATA; ECCN_US: EAR99; ECCN_EU: NEC; Provided_By: SUBCO
CN3 CN4 = MCD-01332: Pin header, 15x1, 2,54mm, VR, TH, Height 6mm/6mm; Part_Type: Connector; Manufacturer_Part_Number: 313115S161145; Manufacturer: LYCONN; Alternate_Manufacturer_Part_Number: TSW 115-08-F-S; Alternate_Manufacturer: SAMTEC; Provided_By: SUBCO
D4 D5 = MCD-01059: LOW DROP POWER SCHOTTKY RECTIFIER 1A 30V VF=0.3V; Part_Type: Diode; Manufacturer: STMICROELECTRONICS; BMS_Part_Number: 9151096; Provided_By: SUBCO with ST control; ECCN_US: EAR99; ECCN_EU: NEC
HW4 = MCD-01409: SHUNT 1.27mm BLACK; Part_Type: Mechanical; Manufacturer: W & P Products; Alternate_Manufacturer_Part_Number: M50-1900005; Alternate_Manufacturer: HARWIN; Provided_By: SUBCO
JP1 = MCD-01484: Header 3x1, 1.27mm, RA,SMT, Height 3.18mm; Part_Type: Connector; Manufacturer_Part_Number: TMS-103-03-L-S-RA; Manufacturer: SAMTEC; Provided_By: SUBCO
L1 = MCD-00047: SMD Chip ferrite bead, 600R@100MHz +/-25%, 350mA, 500mohm DC, 0603, T=0.8mm; Part_Type: Inductor; Manufacturer_Part_Number: FCM1608KF-601T03; Manufacturer: TAI-TECH; Provided_By: SUBCO
LD2 = MCD-00322: as LD4 on sheet ST-LinkV2-1_SWIM
LD3 = MCD-00589: LED Green, 0603 SMD, Fw Voltage = 2.8V - 3.6V; Part_Type: Display; Manufacturer_Part_Number: VLMTG1300-GS08; Manufacturer: VISHAY; Alternate_Manufacturer_Part_Number: LG Q396-PS-35; Alternate_Manufacturer: OSRAM OPTO SEMICONDUCTORS; Order_Code_RS: 7730452; Provided_By: SUBCO
Q2 = MCD-01737: as Q1 on sheet ST-LinkV2-1_SWIM
R23 = MCD-00225: Resistor,510R,0603,1%,1/10W; Manufacturer_Part_Number: RC0603FR-07510RL; Manufacturer: YAGEO; Provided_By: SUBCO; ECCN_US: EAR99; ECCN_EU: NEC
R24 = MCD-00070: as R17 on sheet ST-LinkV2-1_SWIM
R25 = MCD-00222: Resistor,47K,0603,1%,1/10W; Manufacturer_Part_Number: RC0603FR-0747KL; Manufacturer: YAGEO; Provided_By: SUBCO; ECCN_US: EAR99; ECCN_EU: NEC
R26 = MCD-00223: Resistor,100K,0603,1%,1/10W; Manufacturer_Part_Number: RC0603FR-07100KL; Manufacturer: YAGEO; Provided_By: SUBCO; ECCN_US: EAR99; ECCN_EU: NEC
SB5 SB7 SB9 SB10 SB12 = MCD-00072: as SB1 on sheet ST-LinkV2-1_SWIM
SB6 SB8 SB11 SB13 = MCD-00071: as SB3 on sheet ST-LinkV2-1_SWIM
U5 = MCD-01331: IC, STM8S207K8T6, STM8S 8-bit MCU, 64 KB Flash, Performance line, 24 MHz; Manufacturer: STMICROELECTRONICS; Provided_By: SUBCO with ST control; ECCN_US: EAR99; ECCN_EU: NEC
U6 = MCD-00088: IC REG LDO 5V 0.8A SOT223; Manufacturer: STMICROELECTRONICS; BMS_Part_Number: 9176133; ECCN_US: EAR99; ECCN_EU: NEC; Provided_By: SUBCO with ST control
U7 = MCD-00215: Low quiescent current and low noise voltage regulators; Part_Type: IC; Manufacturer: STMICROELECTRONICS; BMS_Part_Number: 9176126; ECCN_US: EAR99; ECCN_EU: NEC; Provided_By: SUBCO with ST control

## Sheet Mechanical.SchDoc: Mechanical
size A4; Date: Not used; ApprovedBy: Not used; CheckedBy: Not used; Author: Not used; CompanyName: STMicroelectronics; DrawnBy: Not used; Engineer: Not used; Organization: Not used; Address1: Not used; Address2: Not used; Address3: Not used; Address4: Not used; DocumentNumber: Not used; Revision: Not used; SheetNumber: 5; SheetTotal: 5
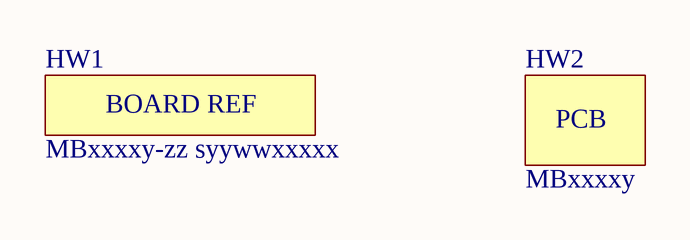
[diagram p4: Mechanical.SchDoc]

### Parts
HW1  value MBxxxxy-zz syywwxxxxx  [STICKER_25X9]  (hidden comment: STICKER_BOARD_REF)  (no BOM)
HW2  value MBxxxxy  (hidden comment: PCB)  (mechanical)

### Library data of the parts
HW1 = MCD-00235: Sticker to mention board reference + serial number; Part_Type: Mechanical; Provided_By: SUBCO
HW2 = MCD-00216: PCB, xxxx for PCB number, Y for PCB revision; Part_Type: Mechanical; Provided_By: SUBCO

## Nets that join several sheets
5V: ST-LinkV2-1_SWIM (D1.1), MCU_Power_IOs_Arduino (9 pins)
5V_ST_LINK_SW: ST-LinkV2-1_SWIM (C10.2 U2.1), MCU_Power_IOs_Arduino (D5.1)
5V_VIN: ST-LinkV2-1_SWIM (D3.1), MCU_Power_IOs_Arduino (C24.2 D4.1 U6.2 U6.4)
GND: ST-LinkV2-1_SWIM (40 pins), MCU_Power_IOs_Arduino (22 pins)
VDD: ST-LinkV2-1_SWIM (R3.2 R14.1), MCU_Power_IOs_Arduino (7 pins)
T_MCO: ST-LinkV2-1_SWIM (C8.2 R13.2), MCU_Power_IOs_Arduino (SB5.1)
T_NRST: ST-LinkV2-1_SWIM (R9.2), MCU_Power_IOs_Arduino (5 pins)
T_SWIM: ST-LinkV2-1_SWIM (R6.2), MCU_Power_IOs_Arduino (U5.26)
T_VCP_RX: ST-LinkV2-1_SWIM (SB3.1), MCU_Power_IOs_Arduino (SB9.1 U5.31)
T_VCP_TX: ST-LinkV2-1_SWIM (SB4.1), MCU_Power_IOs_Arduino (SB7.1 U5.30)

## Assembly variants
S207K8: not fitted C8 CN2 R10 SB1 SB2 SB5 SB7 SB9 SB10 SB12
